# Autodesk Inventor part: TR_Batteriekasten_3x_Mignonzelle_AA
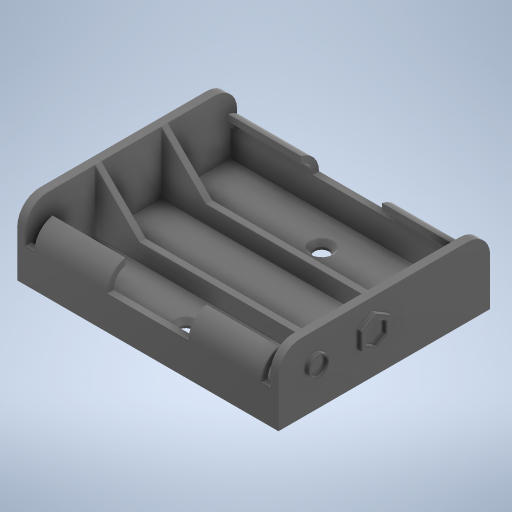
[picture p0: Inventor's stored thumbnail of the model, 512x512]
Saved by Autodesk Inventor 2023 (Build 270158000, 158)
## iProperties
Created: 2023-11
Part Number: TR_Batteriekasten_3x_Mignonzelle_AA
Material: PC/ABS-Kunststoff
Document SubType Name: Modeling
Designer: Greiner
Density: 0.357273 g/cm^3
Appearance: Glatt - Dunkelgrau
Author: Greiner
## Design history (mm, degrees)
sketch "Skizze1"
  geometry: L1 (29, 23.5)-(-29, 23.5); L2 (-29, 23.5)-(-29, -23.5); L3 (-29, -23.5)-(29, -23.5); L4 (29, -23.5)-(29, 23.5); L5 (29, 23.5)-(-29, -23.5); L6 (-29, 23.5)-(29, -23.5); 1 further point
  constraints: 12 end point, 2 midpoint, 2 parallel, 1 horizontal, 1 perpendicular
  dimensions: "d0" = 58 distance of L1.start L1.end; "d1" = 47 distance of L3.end L1.start
extrude "Extrusion1" new body sketch "Skizze1" distance "d2" = 1.5; taper "d3" = 0 deg
sketch "Skizze2"
  geometry: L1 (0, 0)-(47, 0) reference; L2 (0, 0)-(47, 0); L3 (47, 0)-(47, 10.4); L4 (5, 15.4)-(42, 15.4); L5 (0, 0)-(0, 10.4); A1 r 5 centre (5, 10.4) between (5, 15.4) and (0, 10.4); A2 r 5 centre (42, 10.4) between (47, 10.4) and (42, 15.4); 1 further point
  constraints: 8 end point, 4 point on circle, 4 tangent, 2 centre point, 2 horizontal, 1 perpendicular, 1 vertical
  dimensions: "r" = 5 radius of A1; "d5" = 5 radius of A2 (= r); "d6" = 15.4 distance between parallel lines of L1 L4
extrude "Extrusion2" join sketch "Skizze2" distance "d7" = 1.8; taper "d8" = 0 deg
mirror "Spiegeln1"
sketch "Skizze3"
  geometry: L1 (0, 23.5)-(7.5, 23.5); L2 (7.5, 22.1)-(0, 22.1); L3 (0, -23.5)-(0, 23.5) reference; L4 (12.399, 19.5)-(10.958, 19.5); L5 (0, 23.5)-(0, 22.1); L6 (0, 23.5)-(10.4, 23.5) reference; A1 r 5 centre (7.5, 18.5) between (12.399, 19.5) and (7.5, 23.5); A2 r 3.6 centre (7.5, 18.5) between (10.958, 19.5) and (7.5, 22.1); 1 further point
  constraints: 8 end point, 4 point on circle, 3 horizontal, 2 centre point, 2 point on line, 2 tangent, 1 coincident, 1 vertical, 1 vertical alignment
  dimensions: "d9" = 1.4 distance between parallel lines of L1 L2; "d10" = 7.5 distance of L1.start L1.end; "d12" = 5 radius of A1; "d14" = 4 vertical distance of L1.end L4.end
extrude "Extrusion3" join sketch "Skizze3" stored distance "d15" = 56; taper "d16" = 0 deg
mirror "Spiegeln2"
sketch "Skizze4"
  geometry: L1 (-25.2, 7.5)-(-27.2, 7.5); L2 (-27.2, 7.5)-(-27.2, 15.4); L3 (-27.2, 15.4)-(-25.2, 15.4); L4 (-25.2, 15.4)-(-25.2, 7.5); L5 (-27.2, 7.5)-(27.2, 7.5) reference; L6 (-9, 15.4)-(9, 15.4); L7 (9, 15.4)-(9, 7.5); L8 (9, 7.5)-(-9, 7.5); L9 (-9, 7.5)-(-9, 15.4); L10 (-29, 0)-(29, 0) reference; L11 (27.2, 15.4)-(25.2, 15.4); L12 (25.2, 15.4)-(25.2, 7.5); L13 (25.2, 7.5)-(27.2, 7.5); L14 (27.2, 7.5)-(27.2, 15.4); 7 further points
  constraints: 24 end point, 6 parallel, 3 horizontal, 3 perpendicular, 3 point on line, 2 coincident, 2 midpoint, 1 horizontal alignment, 1 vertical alignment
  dimensions: "d17" = 2 distance of L2.end L3.end; "d18" = 18 distance of L6.start L6.end; "d19" = 2 distance of L11.start L11.end
extrude "Extrusion4" cut sketch "Skizze4" extent not by distance; stored distance "d20" = 0; taper "d21" = 0 deg
sketch "Skizze5"
  geometry: L1 (-3.6, -13.9)-(40.6, -13.9) reference; L2 (-3.6, -13.9)-(-3.6, -7.9) reference; L3 (-3.6, -7.9)-(11.133, -7.9); L4 (11.133, -7.9)-(25.867, -7.9); L5 (25.867, -7.9)-(40.6, -7.9); 2 further points
  constraints: 6 end point, 2 collinear, 1 coincident, 1 horizontal, 1 point on line
workplane "Arbeitsebene1"
sketch "Skizze6"
  geometry: L1 (0, -6)-(54.4, -6) reference; L2 (0, 7.9)-(0, 2.9) reference; L3 (0, -6)-(0, 7.9); L4 (0, 7.9)-(9.9, -2); L5 (9.9, -2)-(44.5, -2); L6 (44.5, -2)-(54.4, 7.9); L7 (54.4, 7.9)-(54.4, -6); L8 (54.4, -6)-(0, -6); 4 further points
  constraints: 12 end point, 2 perpendicular, 1 coincident, 1 collinear, 1 parallel
  dimensions: "d23" = 45 deg angle of L3 L4; "d24" = 135 deg angle of L6 L5; "d25" = 4 distance between parallel lines of L1 L5
extrude "Extrusion5" join sketch "Skizze6" stored distance "d26" = 1.4; taper "d27" = 0 deg
mirror "Spiegeln3"
sketch "Skizze7"
  geometry: L1 (23.95, 7.124)-(20.7, 5.247); L2 (20.7, 5.247)-(17.45, 7.124); L3 (17.45, 7.124)-(17.45, 10.876); L4 (17.45, 10.876)-(20.7, 12.753); L5 (20.7, 12.753)-(23.95, 10.876); L6 (23.95, 10.876)-(23.95, 7.124); L7 (22.95, 7.701)-(20.7, 6.402); L8 (20.7, 6.402)-(18.45, 7.701); L9 (18.45, 7.701)-(18.45, 10.299); L10 (18.45, 10.299)-(20.7, 11.598); L11 (20.7, 11.598)-(22.95, 10.299); L12 (22.95, 10.299)-(22.95, 7.701); L13 (0, 0)-(0, 10.4) reference; L14 (0, 0)-(47, 0) reference; C1 r 2 at (8, 9); C2 r 2.25 at (8, 9); 4 further points
  constraints: 24 end point, 2 centre point, 2 coincident, 2 vertical, 1 horizontal alignment, 1 midpoint, 26 other
  dimensions: "d28" = 12.7 distance of point (20.7, 9) C1.centre; "d29" = 8 distance from line of L13 C1.centre; "d30" = 4 diameter of C1; "d31" = 4.5 diameter of C2; "d32" = 4.5 distance between parallel lines of L12 L9; "d33" = 1 distance between parallel lines of L3 L9; "d34" = 9 vertical distance of point (23.5, 0) C1.centre
extrude "Extrusion6" join sketch "Skizze7" distance "d35" = 1; taper "d36" = 0 deg
sketch "Skizze8"
  geometry: L1 (-27.2, 8.067)-(27.2, 8.067) reference; L2 (27.2, 8.067)-(27.2, 22.1) reference; L3 (27.2, 22.1)-(-27.2, 22.1) reference; L4 (-27.2, 22.1)-(-27.2, 8.067) reference; L5 (0, 22.1)-(0, 8.067); L6 (-17.3, -8.067)-(17.3, -8.067) reference; L7 (0, -8.067)-(0, -22.1); L8 (9, -22.1)-(-9, -22.1) reference; C1 r 1.6 at (0, 15.083); C2 r 1.6 at (0, -15.083); 3 further points
  constraints: 6 midpoint, 4 end point, 2 centre point, 2 coincident, 1 equal radius
  dimensions: "d37" = 3.2 diameter of C1
extrude "Extrusion7" cut sketch "Skizze8" extent not by distance; stored distance "d38" = 0; taper "d39" = 0 deg
chamfer "Fase1" distance "d40" = 1; stored, may be unused: second distance "d41" = 2, angle "d42" = 45 deg
node "Volumenkörper1"
node "Projizierte Kontur1"
